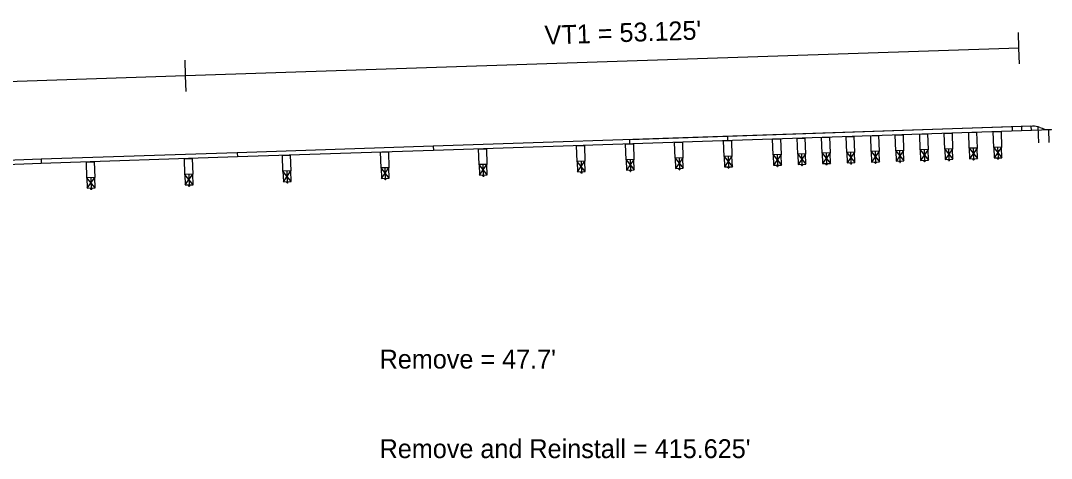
# Model space of a CAD drawing. Extents: x 16537443 to 16538473, y 7054586 to 7055469.
# Drawn here: x 16537878 to 16537943.7, y 7054585.8 to 7054613.7 of the extents above; entities that cross this region are included whole.
import ezdxf

# ---------------------------------------------------------------- set-up
doc = ezdxf.new("R2010")
doc.units = 0
doc.layers.add('Draft_DNC', color=7, linetype='Continuous')

msp = doc.modelspace()

# ---------------------------------------------------------------- linework, layer by layer
at = {"layer": 'Draft_DNC'}
for p, q in [((16537941.648, 7054611.934), (16537941.614, 7054612.933)), ((16537941.648, 7054611.934), (16537888.552, 7054610.163)), ((16537941.681, 7054610.934), (16537941.648, 7054611.934)), ((16537888.552, 7054610.163), (16537888.519, 7054611.162)), ((16537888.552, 7054610.163), (16537526.254, 7054598.077)), ((16537888.585, 7054609.163), (16537888.552, 7054610.163)), ((16537942.514, 7054606.96), (16537904.335, 7054605.687)), ((16537943.718, 7054606.729), (16537904.344, 7054605.416)), ((16537942.418, 7054606.957), (16537916.828, 7054606.103)), ((16537941.21, 7054606.916), (16537941.219, 7054606.646)), ((16537941.814, 7054606.937), (16537941.823, 7054606.666)), ((16537942.418, 7054606.957), (16537942.427, 7054606.686)), ((16537942.912, 7054605.91), (16537942.878, 7054606.912)), ((16537942.979, 7054606.882), (16537943.124, 7054606.831)), ((16537943.467, 7054606.747), (16537943.717, 7054606.755)), ((16537943.578, 7054605.932), (16537943.551, 7054606.75)), ((16537943.718, 7054606.729), (16537943.717, 7054606.755)), ((16537916.828, 7054606.103), (16537916.837, 7054605.833)), ((16537922.834, 7054606.033), (16537923.333, 7054606.049)), ((16537922.867, 7054605.034), (16537922.834, 7054606.033)), ((16537923.075, 7054606.312), (16537923.084, 7054606.041)), ((16537923.333, 7054606.049), (16537923.367, 7054605.05)), ((16537925.957, 7054606.137), (16537926.457, 7054606.154)), ((16537925.99, 7054605.138), (16537925.957, 7054606.137)), ((16537926.457, 7054606.154), (16537926.49, 7054605.155)), ((16537927.519, 7054606.189), (16537928.018, 7054606.206)), ((16537927.552, 7054605.19), (16537927.519, 7054606.189)), ((16537928.018, 7054606.206), (16537928.052, 7054605.207)), ((16537929.08, 7054606.241), (16537929.58, 7054606.258)), ((16537929.08, 7054606.241), (16537929.58, 7054606.258)), ((16537929.114, 7054605.242), (16537929.08, 7054606.241)), ((16537929.114, 7054605.242), (16537929.08, 7054606.241)), ((16537929.58, 7054606.258), (16537929.613, 7054605.259)), ((16537929.58, 7054606.258), (16537929.613, 7054605.259)), ((16537930.642, 7054606.293), (16537931.141, 7054606.31)), ((16537930.675, 7054605.294), (16537930.642, 7054606.293)), ((16537931.141, 7054606.31), (16537931.175, 7054605.311)), ((16537932.204, 7054606.345), (16537932.703, 7054606.362)), ((16537932.237, 7054605.346), (16537932.204, 7054606.345)), ((16537932.703, 7054606.362), (16537932.736, 7054605.363)), ((16537933.765, 7054606.397), (16537934.265, 7054606.414)), ((16537933.799, 7054605.398), (16537933.765, 7054606.397)), ((16537934.265, 7054606.414), (16537934.298, 7054605.415)), ((16537935.327, 7054606.449), (16537935.826, 7054606.466)), ((16537935.36, 7054605.45), (16537935.327, 7054606.449)), ((16537935.826, 7054606.466), (16537935.86, 7054605.467)), ((16537936.889, 7054606.501), (16537937.388, 7054606.518)), ((16537936.922, 7054605.502), (16537936.889, 7054606.501)), ((16537937.388, 7054606.518), (16537937.421, 7054605.519)), ((16537938.45, 7054606.553), (16537938.95, 7054606.57)), ((16537938.483, 7054605.554), (16537938.45, 7054606.553)), ((16537938.95, 7054606.57), (16537938.983, 7054605.571)), ((16537940.012, 7054606.605), (16537940.511, 7054606.622)), ((16537940.045, 7054605.607), (16537940.012, 7054606.605)), ((16537940.511, 7054606.622), (16537940.545, 7054605.623)), ((16537904.335, 7054605.687), (16537891.842, 7054605.27)), ((16537904.344, 7054605.416), (16537891.851, 7054605)), ((16537900.971, 7054605.304), (16537901.471, 7054605.32)), ((16537901.471, 7054605.32), (16537901.504, 7054604.32)), ((16537904.335, 7054605.687), (16537904.344, 7054605.416)), ((16537904.335, 7054605.687), (16537904.344, 7054605.416)), ((16537907.217, 7054605.512), (16537907.717, 7054605.529)), ((16537907.25, 7054604.512), (16537907.217, 7054605.512)), ((16537907.717, 7054605.529), (16537907.751, 7054604.528)), ((16537913.464, 7054605.72), (16537913.964, 7054605.737)), ((16537913.497, 7054604.72), (16537913.464, 7054605.72)), ((16537913.964, 7054605.737), (16537913.997, 7054604.737)), ((16537916.587, 7054605.824), (16537917.087, 7054605.841)), ((16537916.621, 7054604.826), (16537916.587, 7054605.824)), ((16537917.087, 7054605.841), (16537917.12, 7054604.842)), ((16537919.711, 7054605.929), (16537920.21, 7054605.945)), ((16537919.744, 7054604.93), (16537919.711, 7054605.929)), ((16537920.21, 7054605.945), (16537920.243, 7054604.946)), ((16537932.736, 7054605.363), (16537932.237, 7054605.346)), ((16537932.237, 7054605.346), (16537932.759, 7054604.697)), ((16537932.737, 7054605.363), (16537932.259, 7054604.68)), ((16537932.487, 7054605.355), (16537932.509, 7054604.688)), ((16537934.298, 7054605.415), (16537933.799, 7054605.398)), ((16537933.799, 7054605.398), (16537934.321, 7054604.749)), ((16537934.298, 7054605.415), (16537933.821, 7054604.732)), ((16537934.048, 7054605.407), (16537934.071, 7054604.74)), ((16537935.86, 7054605.467), (16537935.36, 7054605.45)), ((16537935.36, 7054605.45), (16537935.882, 7054604.801)), ((16537935.86, 7054605.467), (16537935.382, 7054604.784)), ((16537935.61, 7054605.459), (16537935.632, 7054604.792)), ((16537937.421, 7054605.519), (16537936.922, 7054605.502)), ((16537936.922, 7054605.502), (16537937.444, 7054604.853)), ((16537937.422, 7054605.519), (16537936.944, 7054604.836)), ((16537937.172, 7054605.511), (16537937.194, 7054604.844)), ((16537938.983, 7054605.571), (16537938.483, 7054605.554)), ((16537938.483, 7054605.554), (16537939.005, 7054604.905)), ((16537938.983, 7054605.571), (16537938.506, 7054604.888)), ((16537938.733, 7054605.563), (16537938.756, 7054604.897)), ((16537940.545, 7054605.623), (16537940.045, 7054605.607)), ((16537940.045, 7054605.607), (16537940.567, 7054604.957)), ((16537940.545, 7054605.623), (16537940.067, 7054604.94)), ((16537940.295, 7054605.615), (16537940.317, 7054604.949)), ((16537879.349, 7054604.854), (16537866.856, 7054604.437)), ((16537891.842, 7054605.27), (16537879.349, 7054604.854)), ((16537879.349, 7054604.854), (16537879.358, 7054604.583)), ((16537879.349, 7054604.854), (16537879.358, 7054604.583)), ((16537891.851, 7054605), (16537879.358, 7054604.583)), ((16537882.231, 7054604.679), (16537882.731, 7054604.696)), ((16537882.264, 7054603.679), (16537882.231, 7054604.679)), ((16537882.731, 7054604.696), (16537882.764, 7054603.695)), ((16537888.478, 7054604.887), (16537888.978, 7054604.904)), ((16537888.511, 7054603.887), (16537888.478, 7054604.887)), ((16537888.978, 7054604.904), (16537889.011, 7054603.904)), ((16537891.842, 7054605.27), (16537891.851, 7054605)), ((16537891.842, 7054605.27), (16537891.851, 7054605)), ((16537894.724, 7054605.096), (16537895.224, 7054605.112)), ((16537894.757, 7054604.095), (16537894.724, 7054605.096)), ((16537895.224, 7054605.112), (16537895.258, 7054604.112)), ((16537901.004, 7054604.304), (16537900.971, 7054605.304)), ((16537913.997, 7054604.737), (16537913.497, 7054604.72)), ((16537914.019, 7054604.07), (16537913.497, 7054604.72)), ((16537913.52, 7054604.054), (16537913.997, 7054604.737)), ((16537913.747, 7054604.728), (16537913.769, 7054604.062)), ((16537917.12, 7054604.842), (16537916.621, 7054604.826)), ((16537916.621, 7054604.826), (16537917.143, 7054604.176)), ((16537917.12, 7054604.842), (16537916.643, 7054604.159)), ((16537916.871, 7054604.834), (16537916.893, 7054604.168)), ((16537920.243, 7054604.946), (16537919.744, 7054604.93)), ((16537919.744, 7054604.93), (16537920.266, 7054604.28)), ((16537920.244, 7054604.946), (16537919.766, 7054604.263)), ((16537919.994, 7054604.938), (16537920.016, 7054604.272)), ((16537923.367, 7054605.05), (16537922.867, 7054605.034)), ((16537922.867, 7054605.034), (16537923.389, 7054604.384)), ((16537923.367, 7054605.05), (16537922.889, 7054604.368)), ((16537923.117, 7054605.042), (16537923.139, 7054604.376)), ((16537926.49, 7054605.155), (16537925.99, 7054605.138)), ((16537925.99, 7054605.138), (16537926.512, 7054604.488)), ((16537926.49, 7054605.155), (16537926.013, 7054604.472)), ((16537926.24, 7054605.146), (16537926.262, 7054604.48)), ((16537928.052, 7054605.207), (16537927.552, 7054605.19)), ((16537927.552, 7054605.19), (16537928.074, 7054604.54)), ((16537928.052, 7054605.207), (16537927.574, 7054604.524)), ((16537927.802, 7054605.198), (16537927.824, 7054604.532)), ((16537929.613, 7054605.259), (16537929.114, 7054605.242)), ((16537929.613, 7054605.259), (16537929.114, 7054605.242)), ((16537929.114, 7054605.242), (16537929.636, 7054604.592)), ((16537929.613, 7054605.259), (16537929.136, 7054604.576)), ((16537929.364, 7054605.25), (16537929.386, 7054604.584)), ((16537931.175, 7054605.311), (16537930.675, 7054605.294)), ((16537930.675, 7054605.294), (16537931.197, 7054604.645)), ((16537931.175, 7054605.311), (16537930.698, 7054604.628)), ((16537930.925, 7054605.302), (16537930.947, 7054604.636)), ((16537932.259, 7054604.68), (16537932.759, 7054604.697)), ((16537932.429, 7054604.686), (16537932.43, 7054604.669)), ((16537932.43, 7054604.669), (16537932.59, 7054604.674)), ((16537932.47, 7054604.67), (16537932.471, 7054604.633)), ((16537932.486, 7054604.671), (16537932.487, 7054604.634)), ((16537932.534, 7054604.673), (16537932.535, 7054604.635)), ((16537932.55, 7054604.673), (16537932.551, 7054604.636)), ((16537932.589, 7054604.691), (16537932.59, 7054604.674)), ((16537933.821, 7054604.732), (16537934.321, 7054604.749)), ((16537933.991, 7054604.738), (16537933.991, 7054604.721)), ((16537933.991, 7054604.721), (16537934.151, 7054604.726)), ((16537934.031, 7054604.722), (16537934.032, 7054604.685)), ((16537934.032, 7054604.685), (16537934.112, 7054604.688)), ((16537934.047, 7054604.723), (16537934.048, 7054604.686)), ((16537934.062, 7054604.686), (16537934.063, 7054604.657)), ((16537934.082, 7054604.687), (16537934.083, 7054604.657)), ((16537934.095, 7054604.725), (16537934.096, 7054604.687)), ((16537934.111, 7054604.725), (16537934.112, 7054604.688)), ((16537934.151, 7054604.743), (16537934.151, 7054604.726)), ((16537935.382, 7054604.784), (16537935.882, 7054604.801)), ((16537935.552, 7054604.79), (16537935.553, 7054604.773)), ((16537935.553, 7054604.773), (16537935.713, 7054604.779)), ((16537935.593, 7054604.775), (16537935.594, 7054604.737)), ((16537935.594, 7054604.737), (16537935.674, 7054604.74)), ((16537935.609, 7054604.775), (16537935.61, 7054604.738)), ((16537935.624, 7054604.738), (16537935.625, 7054604.709)), ((16537935.625, 7054604.709), (16537935.645, 7054604.709)), ((16537935.644, 7054604.739), (16537935.645, 7054604.709)), ((16537935.657, 7054604.777), (16537935.658, 7054604.739)), ((16537935.673, 7054604.777), (16537935.674, 7054604.74)), ((16537935.712, 7054604.795), (16537935.713, 7054604.779)), ((16537936.944, 7054604.836), (16537937.444, 7054604.853)), ((16537937.114, 7054604.842), (16537937.114, 7054604.825)), ((16537937.114, 7054604.825), (16537937.274, 7054604.831)), ((16537937.154, 7054604.827), (16537937.156, 7054604.789)), ((16537937.156, 7054604.789), (16537937.236, 7054604.792)), ((16537937.17, 7054604.827), (16537937.172, 7054604.79)), ((16537937.186, 7054604.79), (16537937.187, 7054604.761)), ((16537937.187, 7054604.761), (16537937.207, 7054604.761)), ((16537937.206, 7054604.791), (16537937.207, 7054604.761)), ((16537937.218, 7054604.829), (16537937.22, 7054604.791)), ((16537937.234, 7054604.829), (16537937.236, 7054604.792)), ((16537937.274, 7054604.847), (16537937.274, 7054604.831)), ((16537938.506, 7054604.888), (16537939.005, 7054604.905)), ((16537938.676, 7054604.894), (16537938.676, 7054604.877)), ((16537938.676, 7054604.877), (16537938.836, 7054604.883)), ((16537938.716, 7054604.879), (16537938.717, 7054604.841)), ((16537938.717, 7054604.841), (16537938.797, 7054604.844)), ((16537938.732, 7054604.879), (16537938.733, 7054604.842)), ((16537938.747, 7054604.842), (16537938.748, 7054604.813)), ((16537938.748, 7054604.813), (16537938.768, 7054604.814)), ((16537938.767, 7054604.843), (16537938.768, 7054604.814)), ((16537938.78, 7054604.881), (16537938.781, 7054604.843)), ((16537938.796, 7054604.881), (16537938.797, 7054604.844)), ((16537938.835, 7054604.899), (16537938.836, 7054604.883)), ((16537940.067, 7054604.94), (16537940.567, 7054604.957)), ((16537940.237, 7054604.946), (16537940.238, 7054604.929)), ((16537940.238, 7054604.929), (16537940.398, 7054604.935)), ((16537940.278, 7054604.931), (16537940.279, 7054604.893)), ((16537940.279, 7054604.893), (16537940.359, 7054604.896)), ((16537940.294, 7054604.931), (16537940.295, 7054604.894)), ((16537940.309, 7054604.894), (16537940.31, 7054604.865)), ((16537940.31, 7054604.865), (16537940.33, 7054604.866)), ((16537940.329, 7054604.895), (16537940.33, 7054604.866)), ((16537940.342, 7054604.933), (16537940.343, 7054604.895)), ((16537940.358, 7054604.933), (16537940.359, 7054604.896)), ((16537940.397, 7054604.951), (16537940.398, 7054604.935)), ((16537879.358, 7054604.583), (16537866.865, 7054604.167)), ((16537895.258, 7054604.112), (16537894.757, 7054604.095)), ((16537895.28, 7054603.446), (16537894.758, 7054604.095)), ((16537894.78, 7054603.429), (16537895.258, 7054604.112)), ((16537895.008, 7054604.104), (16537895.03, 7054603.437)), ((16537901.504, 7054604.32), (16537901.004, 7054604.304)), ((16537901.526, 7054603.654), (16537901.004, 7054604.304)), ((16537901.027, 7054603.637), (16537901.504, 7054604.32)), ((16537901.254, 7054604.312), (16537901.276, 7054603.646)), ((16537907.751, 7054604.528), (16537907.25, 7054604.512)), ((16537907.773, 7054603.862), (16537907.251, 7054604.512)), ((16537907.273, 7054603.845), (16537907.751, 7054604.528)), ((16537907.501, 7054604.52), (16537907.523, 7054603.854)), ((16537916.643, 7054604.159), (16537917.143, 7054604.176)), ((16537916.813, 7054604.165), (16537916.813, 7054604.148)), ((16537916.813, 7054604.148), (16537916.973, 7054604.154)), ((16537916.853, 7054604.15), (16537916.855, 7054604.112)), ((16537916.855, 7054604.112), (16537916.934, 7054604.115)), ((16537916.869, 7054604.15), (16537916.871, 7054604.113)), ((16537916.885, 7054604.113), (16537916.885, 7054604.084)), ((16537916.885, 7054604.084), (16537916.905, 7054604.085)), ((16537916.905, 7054604.114), (16537916.905, 7054604.085)), ((16537916.917, 7054604.152), (16537916.919, 7054604.114)), ((16537916.933, 7054604.152), (16537916.934, 7054604.115)), ((16537916.973, 7054604.17), (16537916.973, 7054604.154)), ((16537919.766, 7054604.263), (16537920.266, 7054604.28)), ((16537919.936, 7054604.269), (16537919.937, 7054604.253)), ((16537919.937, 7054604.253), (16537920.096, 7054604.258)), ((16537919.977, 7054604.254), (16537919.978, 7054604.216)), ((16537919.978, 7054604.216), (16537920.058, 7054604.219)), ((16537919.993, 7054604.254), (16537919.994, 7054604.217)), ((16537920.008, 7054604.217), (16537920.009, 7054604.188)), ((16537920.009, 7054604.188), (16537920.029, 7054604.189)), ((16537920.028, 7054604.218), (16537920.029, 7054604.189)), ((16537920.041, 7054604.256), (16537920.042, 7054604.219)), ((16537920.057, 7054604.257), (16537920.058, 7054604.219)), ((16537920.096, 7054604.274), (16537920.096, 7054604.258)), ((16537922.889, 7054604.368), (16537923.389, 7054604.384)), ((16537923.059, 7054604.373), (16537923.06, 7054604.357)), ((16537923.06, 7054604.357), (16537923.22, 7054604.362)), ((16537923.1, 7054604.358), (16537923.101, 7054604.321)), ((16537923.101, 7054604.321), (16537923.181, 7054604.323)), ((16537923.116, 7054604.359), (16537923.117, 7054604.321)), ((16537923.131, 7054604.322), (16537923.132, 7054604.292)), ((16537923.132, 7054604.292), (16537923.152, 7054604.293)), ((16537923.151, 7054604.322), (16537923.152, 7054604.293)), ((16537923.164, 7054604.36), (16537923.165, 7054604.323)), ((16537923.18, 7054604.361), (16537923.181, 7054604.323)), ((16537923.219, 7054604.379), (16537923.22, 7054604.362)), ((16537926.013, 7054604.472), (16537926.512, 7054604.488)), ((16537926.183, 7054604.477), (16537926.183, 7054604.461)), ((16537926.183, 7054604.461), (16537926.343, 7054604.466)), ((16537926.223, 7054604.462), (16537926.224, 7054604.425)), ((16537926.224, 7054604.425), (16537926.304, 7054604.427)), ((16537926.239, 7054604.463), (16537926.24, 7054604.425)), ((16537926.254, 7054604.426), (16537926.255, 7054604.396)), ((16537926.255, 7054604.396), (16537926.275, 7054604.397)), ((16537926.274, 7054604.426), (16537926.275, 7054604.397)), ((16537926.287, 7054604.464), (16537926.288, 7054604.427)), ((16537926.303, 7054604.465), (16537926.304, 7054604.427)), ((16537926.342, 7054604.483), (16537926.343, 7054604.466)), ((16537927.574, 7054604.524), (16537928.074, 7054604.54)), ((16537927.744, 7054604.529), (16537927.745, 7054604.513)), ((16537927.745, 7054604.513), (16537927.905, 7054604.518)), ((16537927.785, 7054604.514), (16537927.786, 7054604.477)), ((16537927.786, 7054604.477), (16537927.866, 7054604.479)), ((16537927.801, 7054604.515), (16537927.802, 7054604.477)), ((16537927.816, 7054604.478), (16537927.817, 7054604.448)), ((16537927.817, 7054604.448), (16537927.837, 7054604.449)), ((16537927.836, 7054604.478), (16537927.837, 7054604.449)), ((16537927.849, 7054604.516), (16537927.85, 7054604.479)), ((16537927.865, 7054604.517), (16537927.866, 7054604.479)), ((16537927.904, 7054604.535), (16537927.905, 7054604.518)), ((16537929.136, 7054604.576), (16537929.636, 7054604.592)), ((16537929.306, 7054604.581), (16537929.306, 7054604.565)), ((16537929.306, 7054604.565), (16537929.466, 7054604.57)), ((16537929.346, 7054604.566), (16537929.348, 7054604.529)), ((16537929.348, 7054604.529), (16537929.428, 7054604.532)), ((16537929.362, 7054604.567), (16537929.364, 7054604.529)), ((16537929.378, 7054604.53), (16537929.379, 7054604.5)), ((16537929.379, 7054604.5), (16537929.399, 7054604.501)), ((16537929.398, 7054604.531), (16537929.399, 7054604.501)), ((16537929.41, 7054604.568), (16537929.412, 7054604.531)), ((16537929.426, 7054604.569), (16537929.428, 7054604.532)), ((16537929.466, 7054604.587), (16537929.466, 7054604.57)), ((16537930.698, 7054604.628), (16537931.197, 7054604.645)), ((16537930.867, 7054604.634), (16537930.868, 7054604.617)), ((16537930.868, 7054604.617), (16537931.028, 7054604.622)), ((16537930.908, 7054604.618), (16537930.909, 7054604.581)), ((16537930.909, 7054604.581), (16537930.989, 7054604.584)), ((16537930.924, 7054604.619), (16537930.925, 7054604.581)), ((16537930.939, 7054604.582), (16537930.94, 7054604.553)), ((16537930.94, 7054604.553), (16537930.96, 7054604.553)), ((16537930.959, 7054604.583), (16537930.96, 7054604.553)), ((16537930.972, 7054604.62), (16537930.973, 7054604.583)), ((16537930.988, 7054604.621), (16537930.989, 7054604.584)), ((16537931.027, 7054604.639), (16537931.028, 7054604.622)), ((16537932.471, 7054604.633), (16537932.551, 7054604.636)), ((16537932.501, 7054604.634), (16537932.502, 7054604.605)), ((16537932.502, 7054604.605), (16537932.522, 7054604.605)), ((16537932.521, 7054604.635), (16537932.522, 7054604.605)), ((16537934.063, 7054604.657), (16537934.083, 7054604.657)), ((16537882.764, 7054603.695), (16537882.264, 7054603.679)), ((16537882.787, 7054603.029), (16537882.265, 7054603.679)), ((16537882.287, 7054603.012), (16537882.764, 7054603.695)), ((16537882.515, 7054603.687), (16537882.537, 7054603.021)), ((16537889.011, 7054603.904), (16537888.511, 7054603.887)), ((16537889.033, 7054603.237), (16537888.511, 7054603.887)), ((16537888.534, 7054603.221), (16537889.011, 7054603.904)), ((16537888.761, 7054603.895), (16537888.783, 7054603.229)), ((16537901.28, 7054603.548), (16537901.28, 7054603.541)), ((16537907.526, 7054603.757), (16537907.526, 7054603.75)), ((16537913.773, 7054603.965), (16537913.773, 7054603.958)), ((16537882.54, 7054602.924), (16537882.54, 7054602.917)), ((16537888.787, 7054603.132), (16537888.787, 7054603.125)), ((16537895.033, 7054603.34), (16537895.033, 7054603.333))]:
    msp.add_line(p, q, dxfattribs=at)
for points in [[(16537932.737, 7054605.363), (16537932.237, 7054605.346), (16537932.259, 7054604.68), (16537932.759, 7054604.697)], [(16537934.298, 7054605.415), (16537933.799, 7054605.398), (16537933.821, 7054604.732), (16537934.321, 7054604.749)], [(16537935.86, 7054605.467), (16537935.36, 7054605.45), (16537935.382, 7054604.784), (16537935.882, 7054604.801)], [(16537937.422, 7054605.519), (16537936.922, 7054605.502), (16537936.944, 7054604.836), (16537937.444, 7054604.853)], [(16537938.983, 7054605.571), (16537938.483, 7054605.554), (16537938.506, 7054604.888), (16537939.005, 7054604.905)], [(16537940.545, 7054605.623), (16537940.045, 7054605.607), (16537940.067, 7054604.94), (16537940.567, 7054604.957)], [(16537913.997, 7054604.737), (16537913.497, 7054604.72), (16537913.52, 7054604.054), (16537914.019, 7054604.07)], [(16537917.12, 7054604.842), (16537916.621, 7054604.826), (16537916.643, 7054604.159), (16537917.143, 7054604.176)], [(16537920.244, 7054604.946), (16537919.744, 7054604.93), (16537919.766, 7054604.263), (16537920.266, 7054604.28)], [(16537923.367, 7054605.05), (16537922.867, 7054605.034), (16537922.889, 7054604.368), (16537923.389, 7054604.384)], [(16537926.49, 7054605.155), (16537925.99, 7054605.138), (16537926.013, 7054604.472), (16537926.512, 7054604.488)], [(16537928.052, 7054605.207), (16537927.552, 7054605.19), (16537927.574, 7054604.524), (16537928.074, 7054604.54)], [(16537929.613, 7054605.259), (16537929.114, 7054605.242), (16537929.136, 7054604.576), (16537929.636, 7054604.592)], [(16537931.175, 7054605.311), (16537930.675, 7054605.294), (16537930.698, 7054604.628), (16537931.197, 7054604.645)], [(16537895.258, 7054604.112), (16537894.758, 7054604.095), (16537894.78, 7054603.429), (16537895.28, 7054603.446)], [(16537901.504, 7054604.32), (16537901.004, 7054604.304), (16537901.027, 7054603.637), (16537901.526, 7054603.654)], [(16537907.751, 7054604.528), (16537907.251, 7054604.512), (16537907.273, 7054603.845), (16537907.773, 7054603.862)], [(16537882.764, 7054603.695), (16537882.265, 7054603.679), (16537882.287, 7054603.012), (16537882.787, 7054603.029)], [(16537889.011, 7054603.904), (16537888.511, 7054603.887), (16537888.534, 7054603.221), (16537889.033, 7054603.237)]]:
    msp.add_lwpolyline(points, close=True, dxfattribs=at)
for points in [[(16537913.803, 7054604.063), (16537913.804, 7054604.02), (16537913.738, 7054604.018), (16537913.736, 7054604.061)], [(16537913.79, 7054604.02), (16537913.792, 7054603.966), (16537913.753, 7054603.964), (16537913.751, 7054604.018)], [(16537895.063, 7054603.438), (16537895.065, 7054603.395), (16537894.998, 7054603.393), (16537894.997, 7054603.436)], [(16537895.051, 7054603.395), (16537895.053, 7054603.341), (16537895.014, 7054603.339), (16537895.012, 7054603.394)], [(16537901.31, 7054603.647), (16537901.311, 7054603.604), (16537901.245, 7054603.601), (16537901.243, 7054603.644)], [(16537901.297, 7054603.603), (16537901.299, 7054603.549), (16537901.26, 7054603.548), (16537901.258, 7054603.602)], [(16537907.556, 7054603.855), (16537907.558, 7054603.812), (16537907.491, 7054603.81), (16537907.49, 7054603.853)], [(16537907.544, 7054603.811), (16537907.546, 7054603.757), (16537907.507, 7054603.756), (16537907.505, 7054603.81)], [(16537882.57, 7054603.022), (16537882.572, 7054602.979), (16537882.505, 7054602.977), (16537882.504, 7054603.02)], [(16537882.558, 7054602.978), (16537882.56, 7054602.924), (16537882.521, 7054602.923), (16537882.519, 7054602.977)], [(16537888.817, 7054603.23), (16537888.818, 7054603.187), (16537888.751, 7054603.185), (16537888.75, 7054603.228)], [(16537888.804, 7054603.187), (16537888.806, 7054603.133), (16537888.767, 7054603.131), (16537888.765, 7054603.185)]]:
    msp.add_lwpolyline(points, dxfattribs=at)
for centre, major_axis, start_param, end_param in [((16537942.485, 7054605.463), (-1.541, -0.051), 4.353641, 4.660842), ((16537943.635, 7054608.076), (1.378, 0.046), 4.300427, 4.558114)]:
    msp.add_ellipse(centre, major_axis=major_axis, ratio=0.97085, start_param=start_param, end_param=end_param, dxfattribs=at)

# ---------------------------------------------------------------- texts
for s, rotation, p in [("VT1 = 53.125'", 1.91058, (16537911.447, 7054612.152)), ("Remove = 47.7'", 0.00101, (16537900.915, 7054591.53)), ("Remove and Reinstall = 415.625'", 0.00101, (16537900.915, 7054585.83))]:
    msp.add_text(s, height=1.2, rotation=rotation, dxfattribs=at).set_placement(p)

doc.saveas('drawing.dxf')
